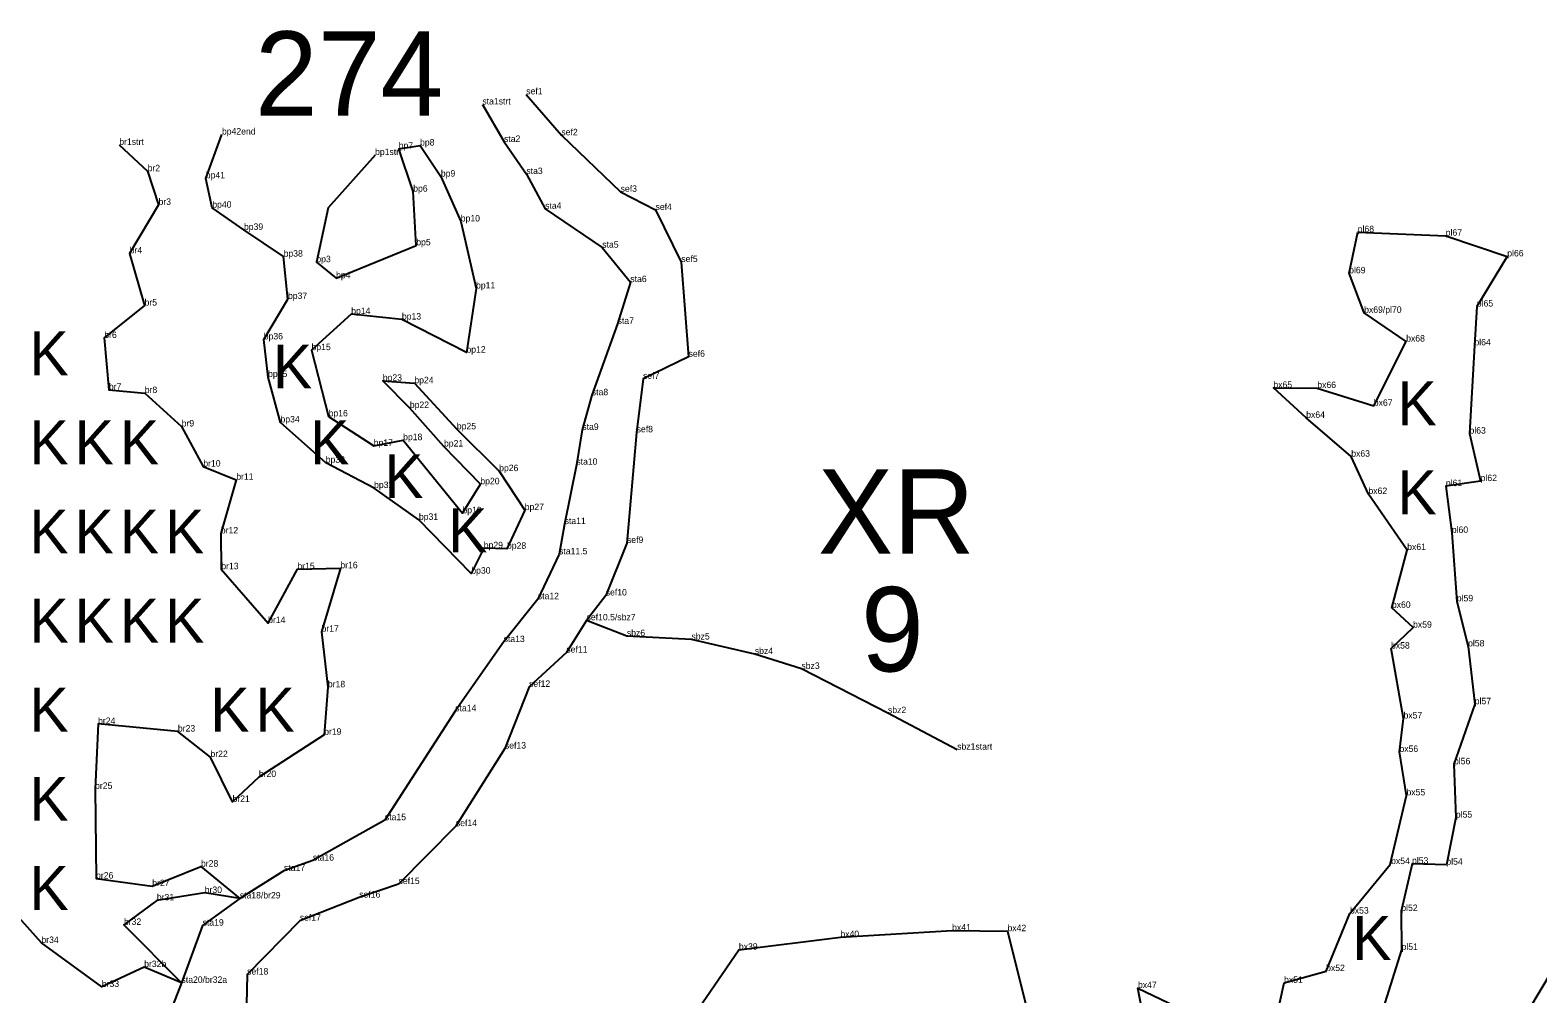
# Model space of a CAD drawing. Extents: x 2072529 to 2268812, y 436423 to 470008.
# Drawn here: x 2233102 to 2234269, y 438303 to 439049 of the extents above; entities that cross this region are included whole.
import ezdxf

# ---------------------------------------------------------------- set-up
doc = ezdxf.new("R2010")
doc.units = 0
for name, color, linetype in [('Old_Level_10', 7, 'Continuous'), ('Old_Level_20', 7, 'Continuous'), ('Old_Level_52', 7, 'Continuous'), ('Old_Level_55', 7, 'Continuous'), ('Old_Level_60', 7, 'Continuous'), ('Old_Level_62', 7, 'Continuous')]:
    doc.layers.add(name, color=color, linetype=linetype)

msp = doc.modelspace()

# ---------------------------------------------------------------- linework, layer by layer
at = {"layer": 'Old_Level_10'}
for points in [[(2233452.149, 438991.664), (2233468.903, 438962.649), (2233486.215, 438937.777), (2233500.705, 438910.853), (2233544.956, 438880.766), (2233566.694, 438854.085), (2233556.825, 438821.757), (2233536.872, 438766.484), (2233529.517, 438739.646), (2233524.919, 438712.662), (2233515.837, 438666.685), (2233511.521, 438643.301), (2233495.079, 438608.514), (2233468.612, 438575.331), (2233431.11, 438521.764), (2233376.668, 438437.394), (2233320.946, 438406.056), (2233298.574, 438398.116), (2233264.347, 438376.794), (2233235.564, 438355.78), (2233219.222, 438311.431), (2233210.7, 438289.635)], [(2233486.125, 438999.503), (2233513.334, 438967.786), (2233559.17, 438924.007), (2233586.216, 438909.965), (2233606.162, 438869.63), (2233611.796, 438796.228), (2233576.522, 438779.169), (2233571.575, 438737.748), (2233564.095, 438652.028), (2233547.637, 438611.403), (2233532.819, 438592.148), (2233517.163, 438567.199), (2233488.294, 438540.647), (2233469.596, 438492.881), (2233431.643, 438432.798), (2233387.241, 438387.931), (2233356.82, 438377.469), (2233310.807, 438359.523), (2233270.05, 438317.862), (2233268.69, 438260.03)], [(2233819.709, 438491.998), (2233766.143, 438520.289), (2233699.145, 438554.56), (2233663.079, 438566.07), (2233614.029, 438577.308), (2233564.004, 438579.97), (2233532.819, 438592.148)]]:
    msp.add_lwpolyline(points, dxfattribs=at)
at = {"layer": 'Old_Level_20'}
for p, q in [((2233452.149, 438991.664), (2233452.149, 438991.664)), ((2233486.125, 438999.503), (2233486.125, 438999.503)), ((2233250.54, 438968.368), (2233250.54, 438968.368)), ((2233513.334, 438967.786), (2233513.334, 438967.786)), ((2233171.058, 438960.351), (2233171.058, 438960.351)), ((2233387.354, 438957.417), (2233387.354, 438957.417)), ((2233403.912, 438959.866), (2233403.912, 438959.866)), ((2233468.903, 438962.649), (2233468.903, 438962.649)), ((2233193.012, 438939.927), (2233193.012, 438939.927)), ((2233238.028, 438934.445), (2233238.028, 438934.445)), ((2233420.007, 438935.811), (2233420.007, 438935.811)), ((2233486.215, 438937.777), (2233486.215, 438937.777)), ((2233398.611, 438924.169), (2233398.611, 438924.169)), ((2233559.17, 438924.007), (2233559.17, 438924.007)), ((2233201.424, 438913.897), (2233201.424, 438913.897)), ((2233243.053, 438911.718), (2233243.053, 438911.718)), ((2233500.705, 438910.853), (2233500.705, 438910.853)), ((2233586.216, 438909.965), (2233586.216, 438909.965)), ((2233435.402, 438901.032), (2233435.402, 438901.032)), ((2233267.568, 438894.505), (2233267.568, 438894.505)), ((2234129.797, 438892.773), (2234129.797, 438892.773)), ((2234197.922, 438889.97), (2234197.922, 438889.97)), ((2233179.099, 438876.325), (2233179.099, 438876.325)), ((2233298.26, 438873.801), (2233298.26, 438873.801)), ((2233400.966, 438882.567), (2233400.966, 438882.567)), ((2233544.956, 438880.766), (2233544.956, 438880.766)), ((2234245.56, 438873.979), (2234245.56, 438873.979)), ((2233323.625, 438869.522), (2233323.625, 438869.522)), ((2233606.162, 438869.63), (2233606.162, 438869.63)), ((2233338.88, 438857.064), (2233338.88, 438857.064)), ((2233566.694, 438854.085), (2233566.694, 438854.085)), ((2234123.163, 438860.908), (2234123.163, 438860.908)), ((2233301.659, 438841.001), (2233301.659, 438841.001)), ((2233447.245, 438849.142), (2233447.245, 438849.142)), ((2233190.601, 438835.952), (2233190.601, 438835.952)), ((2233350.609, 438829.324), (2233350.609, 438829.324)), ((2234134.774, 438830.293), (2234134.774, 438830.293)), ((2234221.981, 438835.186), (2234221.981, 438835.186)), ((2233389.864, 438825.117), (2233389.864, 438825.117)), ((2233556.825, 438821.757), (2233556.825, 438821.757)), ((2233159.429, 438810.809), (2233159.429, 438810.809)), ((2233282.914, 438809.689), (2233282.914, 438809.689)), ((2234167.302, 438808.062), (2234167.302, 438808.062)), ((2234220.158, 438805.076), (2234220.158, 438805.076)), ((2233319.872, 438801.388), (2233319.872, 438801.388)), ((2233439.817, 438799.483), (2233439.817, 438799.483)), ((2233611.796, 438796.228), (2233611.796, 438796.228)), ((2233286.242, 438780.557), (2233286.242, 438780.557)), ((2233163.015, 438770.697), (2233163.015, 438770.697)), ((2233190.8, 438768.172), (2233190.8, 438768.172)), ((2233375.063, 438777.665), (2233375.063, 438777.665)), ((2233399.495, 438775.737), (2233399.495, 438775.737)), ((2233576.522, 438779.169), (2233576.522, 438779.169)), ((2234064.502, 438772.209), (2234064.502, 438772.209)), ((2234098.507, 438772.049), (2234098.507, 438772.049)), ((2233395.99, 438756.593), (2233395.99, 438756.593)), ((2233536.872, 438766.484), (2233536.872, 438766.484)), ((2234142.245, 438758.284), (2234142.245, 438758.284)), ((2233295.86, 438745.435), (2233295.86, 438745.435)), ((2233333.112, 438750.109), (2233333.112, 438750.109)), ((2234089.931, 438748.963), (2234089.931, 438748.963)), ((2233219.337, 438742.292), (2233219.337, 438742.292)), ((2233432.367, 438740.095), (2233432.367, 438740.095)), ((2233529.517, 438739.646), (2233529.517, 438739.646)), ((2233571.575, 438737.748), (2233571.575, 438737.748)), ((2234216.328, 438736.768), (2234216.328, 438736.768)), ((2233368.001, 438727.299), (2233368.001, 438727.299)), ((2233390.805, 438731.689), (2233390.805, 438731.689)), ((2233422.421, 438726.764), (2233422.421, 438726.764)), ((2233236.091, 438711.257), (2233236.091, 438711.257)), ((2233330.864, 438714.212), (2233330.864, 438714.212)), ((2233524.919, 438712.662), (2233524.919, 438712.662)), ((2234124.787, 438718.917), (2234124.787, 438718.917)), ((2233261.633, 438701.078), (2233261.633, 438701.078)), ((2233465.139, 438707.705), (2233465.139, 438707.705)), ((2234224.963, 438699.989), (2234224.963, 438699.989)), ((2233368.313, 438694.596), (2233368.313, 438694.596)), ((2233450.581, 438697.522), (2233450.581, 438697.522)), ((2234138.111, 438689.97), (2234138.111, 438689.97)), ((2234198.007, 438696.097), (2234198.007, 438696.097)), ((2233436.707, 438675.091), (2233436.707, 438675.091)), ((2233484.94, 438677.54), (2233484.94, 438677.54)), ((2233403.011, 438669.957), (2233403.011, 438669.957)), ((2233515.837, 438666.685), (2233515.837, 438666.685)), ((2233249.693, 438659.447), (2233249.693, 438659.447)), ((2233564.095, 438652.028), (2233564.095, 438652.028)), ((2234202.646, 438659.862), (2234202.646, 438659.862)), ((2233453.224, 438647.979), (2233453.224, 438647.979)), ((2233471.201, 438647.572), (2233471.201, 438647.572)), ((2233511.521, 438643.301), (2233511.521, 438643.301)), ((2234168.109, 438646.6), (2234168.109, 438646.6)), ((2233250.028, 438631.711), (2233250.028, 438631.711)), ((2233308.925, 438631.758), (2233308.925, 438631.758)), ((2233342.212, 438632.512), (2233342.212, 438632.512)), ((2233443.579, 438628.34), (2233443.579, 438628.34)), ((2233495.079, 438608.514), (2233495.079, 438608.514)), ((2233547.637, 438611.403), (2233547.637, 438611.403)), ((2234206.503, 438606.874), (2234206.503, 438606.874)), ((2234156.263, 438601.829), (2234156.263, 438601.829)), ((2233286.303, 438590.049), (2233286.303, 438590.049)), ((2233327.623, 438583.344), (2233327.623, 438583.344)), ((2233532.819, 438592.148), (2233532.819, 438592.148)), ((2234172.653, 438586.501), (2234172.653, 438586.501)), ((2233468.612, 438575.331), (2233468.612, 438575.331)), ((2233564.004, 438579.97), (2233564.004, 438579.97)), ((2233614.029, 438577.308), (2233614.029, 438577.308)), ((2234155.584, 438570.281), (2234155.584, 438570.281)), ((2234215.251, 438571.962), (2234215.251, 438571.962)), ((2233517.163, 438567.199), (2233517.163, 438567.199)), ((2233663.079, 438566.07), (2233663.079, 438566.07)), ((2233699.145, 438554.56), (2233699.145, 438554.56)), ((2233332.548, 438540.298), (2233332.548, 438540.298)), ((2233488.294, 438540.647), (2233488.294, 438540.647)), ((2234220.377, 438527.179), (2234220.377, 438527.179)), ((2233154.634, 438511.906), (2233154.634, 438511.906)), ((2233431.11, 438521.764), (2233431.11, 438521.764)), ((2233766.143, 438520.289), (2233766.143, 438520.289)), ((2234165.255, 438516.151), (2234165.255, 438516.151)), ((2233216.434, 438506.06), (2233216.434, 438506.06)), ((2233329.678, 438503.54), (2233329.678, 438503.54)), ((2233469.596, 438492.881), (2233469.596, 438492.881)), ((2233819.709, 438491.998), (2233819.709, 438491.998)), ((2234162.115, 438490.258), (2234162.115, 438490.258)), ((2233241.656, 438486.323), (2233241.656, 438486.323)), ((2234204.321, 438480.7), (2234204.321, 438480.7)), ((2233279.123, 438470.844), (2233279.123, 438470.844)), ((2233152.309, 438461.639), (2233152.309, 438461.639)), ((2234167.55, 438456.6), (2234167.55, 438456.6)), ((2233258.712, 438451.546), (2233258.712, 438451.546)), ((2233376.668, 438437.394), (2233376.668, 438437.394)), ((2233431.643, 438432.798), (2233431.643, 438432.798)), ((2234205.768, 438439.368), (2234205.768, 438439.368)), ((2233320.946, 438406.056), (2233320.946, 438406.056)), ((2233234.306, 438401.459), (2233234.306, 438401.459)), ((2233298.574, 438398.116), (2233298.574, 438398.116)), ((2234154.999, 438403.07), (2234154.999, 438403.07)), ((2234171.844, 438403.686), (2234171.844, 438403.686)), ((2234198.431, 438402.887), (2234198.431, 438402.887)), ((2233153.079, 438392.206), (2233153.079, 438392.206)), ((2233196.547, 438386.332), (2233196.547, 438386.332)), ((2233387.241, 438387.931), (2233387.241, 438387.931)), ((2233200.165, 438375.307), (2233200.165, 438375.307)), ((2233237.196, 438381.029), (2233237.196, 438381.029)), ((2233264.347, 438376.794), (2233264.347, 438376.794)), ((2233264.347, 438376.794), (2233264.347, 438376.794)), ((2233356.82, 438377.469), (2233356.82, 438377.469)), ((2233310.807, 438359.523), (2233310.807, 438359.523)), ((2234123.796, 438365.08), (2234123.796, 438365.08)), ((2234163.55, 438367.073), (2234163.55, 438367.073)), ((2233174.653, 438356.346), (2233174.653, 438356.346)), ((2233235.564, 438355.78), (2233235.564, 438355.78)), ((2233815.783, 438351.891), (2233815.783, 438351.891)), ((2233858.656, 438351.453), (2233858.656, 438351.453)), ((2233110.769, 438342.307), (2233110.769, 438342.307)), ((2233650.735, 438337.127), (2233650.735, 438337.127)), ((2233729.33, 438346.824), (2233729.33, 438346.824)), ((2234163.752, 438336.952), (2234163.752, 438336.952)), ((2233190.348, 438323.661), (2233190.348, 438323.661)), ((2233270.05, 438317.862), (2233270.05, 438317.862)), ((2234105.343, 438320.55), (2234105.343, 438320.55)), ((2233157.542, 438308.254), (2233157.542, 438308.254)), ((2233219.222, 438311.431), (2233219.222, 438311.431)), ((2233219.222, 438311.431), (2233219.222, 438311.431)), ((2233959.691, 438307.398), (2233959.691, 438307.398)), ((2234072.757, 438311.451), (2234072.757, 438311.451))]:
    msp.add_line(p, q, dxfattribs=at)
at = {"layer": 'Old_Level_52'}
for points in [[(2233369.084, 438952.484), (2233332.653, 438911.674), (2233323.625, 438869.522), (2233338.88, 438857.064), (2233400.966, 438882.567), (2233398.611, 438924.169), (2233387.354, 438957.417), (2233403.912, 438959.866), (2233420.007, 438935.811), (2233435.402, 438901.032), (2233447.245, 438849.142), (2233439.817, 438799.483), (2233389.864, 438825.117), (2233350.609, 438829.324), (2233319.872, 438801.388), (2233333.112, 438750.109), (2233368.001, 438727.299), (2233390.805, 438731.689), (2233436.707, 438675.091), (2233450.581, 438697.522), (2233422.421, 438726.764), (2233395.99, 438756.593), (2233375.063, 438777.665), (2233399.495, 438775.737), (2233432.367, 438740.095), (2233465.139, 438707.705), (2233484.94, 438677.54), (2233471.201, 438647.572), (2233453.224, 438647.979), (2233443.579, 438628.34), (2233403.011, 438669.957), (2233368.313, 438694.596), (2233330.864, 438714.212), (2233295.86, 438745.435), (2233286.242, 438780.557), (2233282.914, 438809.689), (2233301.659, 438841.001), (2233298.26, 438873.801), (2233267.568, 438894.505), (2233243.053, 438911.718), (2233238.028, 438934.445), (2233250.54, 438968.368)], [(2233171.058, 438960.351), (2233193.012, 438939.927), (2233201.424, 438913.897), (2233179.099, 438876.325), (2233190.601, 438835.952), (2233159.429, 438810.809), (2233163.015, 438770.697), (2233190.8, 438768.172), (2233219.337, 438742.292), (2233236.091, 438711.257), (2233261.633, 438701.078), (2233249.693, 438659.447), (2233250.028, 438631.711), (2233286.303, 438590.049), (2233308.925, 438631.758), (2233342.212, 438632.512), (2233327.623, 438583.344), (2233332.548, 438540.298), (2233329.678, 438503.54), (2233279.123, 438470.844), (2233258.712, 438451.546), (2233241.656, 438486.323), (2233216.434, 438506.06), (2233154.634, 438511.906), (2233152.309, 438461.639), (2233153.079, 438392.206), (2233196.547, 438386.332), (2233234.306, 438401.459), (2233264.347, 438376.794), (2233237.196, 438381.029), (2233200.165, 438375.307), (2233174.653, 438356.346), (2233219.222, 438311.431), (2233190.348, 438323.661), (2233157.542, 438308.254), (2233110.769, 438342.307), (2233071.236, 438386.296)], [(2234059.944, 438252.781), (2234072.757, 438311.451), (2234105.343, 438320.55), (2234123.796, 438365.08), (2234154.999, 438403.07), (2234167.55, 438456.6), (2234162.115, 438490.258), (2234165.255, 438516.151), (2234155.584, 438570.281), (2234172.653, 438586.501), (2234156.263, 438601.829), (2234168.109, 438646.6), (2234138.111, 438689.97), (2234124.787, 438718.917), (2234089.931, 438748.963), (2234064.502, 438772.209), (2234098.507, 438772.049), (2234142.245, 438758.284), (2234167.302, 438808.062), (2234134.774, 438830.293), (2234123.163, 438860.908), (2234129.797, 438892.773), (2234197.922, 438889.97), (2234245.56, 438873.979), (2234221.981, 438835.186), (2234220.158, 438805.076), (2234216.328, 438736.768), (2234224.963, 438699.989), (2234198.007, 438696.097), (2234202.646, 438659.862), (2234206.503, 438606.874)], [(2234206.503, 438606.874), (2234215.251, 438571.962), (2234220.377, 438527.179), (2234204.321, 438480.7), (2234205.768, 438439.368), (2234198.431, 438402.887), (2234171.844, 438403.686), (2234163.55, 438367.073), (2234163.752, 438336.952), (2234149.394, 438291.748), (2234133.006, 438274.68), (2234116.863, 438241.327), (2234090.908, 438214.156), (2234094.319, 438184.72), (2234104.509, 438141.529), (2234133.818, 438128.749), (2234182.336, 438154.843), (2234195.999, 438171.358), (2234239.707, 438238.048), (2234253.57, 438275.929), (2234280.543, 438321.152)], [(2233613.074, 438282.026), (2233650.735, 438337.127), (2233729.33, 438346.824), (2233815.783, 438351.891), (2233858.656, 438351.453), (2233874.615, 438287.265)], [(2233965.718, 438275.421), (2233959.691, 438307.398), (2233989.311, 438293.233)]]:
    msp.add_lwpolyline(points, dxfattribs=at)

# ---------------------------------------------------------------- texts
at = {"layer": 'Old_Level_55'}
for p in [(2233101.528, 438781.933), (2233290.056, 438771.751), (2234160.577, 438743.244), (2233101.528, 438712.933), (2233136.528, 438712.933), (2233171.528, 438712.933), (2233318.795, 438713.022), (2233376.275, 438686.781), (2234160.577, 438674.244), (2233101.528, 438643.933), (2233136.528, 438643.933), (2233171.528, 438643.933), (2233206.528, 438643.933), (2233425.632, 438644.921), (2233101.528, 438574.933), (2233136.528, 438574.933), (2233171.528, 438574.933), (2233206.528, 438574.933), (2233101.528, 438505.933), (2233241.528, 438505.933), (2233276.528, 438505.933), (2233101.528, 438436.933), (2233101.528, 438367.933), (2234125.577, 438329.244)]:
    msp.add_text('K', height=34, dxfattribs=at).set_placement(p)
at = {"layer": 'Old_Level_60'}
for s, p in [('sef1', (2233486.125, 438999.503)), ('sta1strt', (2233452.149, 438991.664)), ('bp42end', (2233250.54, 438968.368)), ('sta2', (2233468.903, 438962.649)), ('sef2', (2233513.334, 438967.786)), ('br1strt', (2233171.058, 438960.351)), ('bp1strt', (2233369.084, 438952.484)), ('bp7', (2233387.354, 438957.417)), ('bp8', (2233403.912, 438959.866)), ('br2', (2233193.012, 438939.927)), ('sta3', (2233486.215, 438937.777)), ('bp41', (2233238.028, 438934.445)), ('bp9', (2233420.007, 438935.811)), ('bp6', (2233398.611, 438924.169)), ('sef3', (2233559.17, 438924.007)), ('br3', (2233201.424, 438913.897)), ('bp40', (2233243.053, 438911.718)), ('sta4', (2233500.705, 438910.853)), ('sef4', (2233586.216, 438909.965)), ('bp39', (2233267.568, 438894.505)), ('bp10', (2233435.402, 438901.032)), ('pl68', (2234129.797, 438892.773)), ('bp5', (2233400.966, 438882.567)), ('sta5', (2233544.956, 438880.766)), ('pl67', (2234197.922, 438889.97)), ('br4', (2233179.099, 438876.325)), ('bp38', (2233298.26, 438873.801)), ('bp3', (2233323.625, 438869.522)), ('sef5', (2233606.162, 438869.63)), ('pl66', (2234245.56, 438873.979)), ('bp4', (2233338.88, 438857.064)), ('pl69', (2234123.163, 438860.908)), ('bp11', (2233447.245, 438849.142)), ('sta6', (2233566.694, 438854.085)), ('br5', (2233190.601, 438835.952)), ('bp37', (2233301.659, 438841.001)), ('pl65', (2234221.981, 438835.186)), ('bp14', (2233350.609, 438829.324)), ('bp13', (2233389.864, 438825.117)), ('sta7', (2233556.825, 438821.757)), ('bx69/pl70', (2234134.774, 438830.293)), ('br6', (2233159.429, 438810.809)), ('bp36', (2233282.914, 438809.689)), ('bp15', (2233319.872, 438801.388)), ('bp12', (2233439.817, 438799.483)), ('bx68', (2234167.302, 438808.062)), ('pl64', (2234220.158, 438805.076)), ('sef6', (2233611.796, 438796.228)), ('bp35', (2233286.242, 438780.557)), ('bp23', (2233375.063, 438777.665)), ('bp24', (2233399.495, 438775.737)), ('sef7', (2233576.522, 438779.169)), ('br7', (2233163.015, 438770.697)), ('br8', (2233190.8, 438768.172)), ('sta8', (2233536.872, 438766.484)), ('bx65', (2234064.502, 438772.209)), ('bx66', (2234098.507, 438772.049)), ('bp22', (2233395.99, 438756.593)), ('bx67', (2234142.245, 438758.284)), ('br9', (2233219.337, 438742.292)), ('bp34', (2233295.86, 438745.435)), ('bp16', (2233333.112, 438750.109)), ('bp25', (2233432.367, 438740.095)), ('sta9', (2233529.517, 438739.646)), ('bx64', (2234089.931, 438748.963)), ('bp18', (2233390.805, 438731.689)), ('sef8', (2233571.575, 438737.748)), ('pl63', (2234216.328, 438736.768)), ('bp17', (2233368.001, 438727.299)), ('bp21', (2233422.421, 438726.764)), ('bx63', (2234124.787, 438718.917)), ('br10', (2233236.091, 438711.257)), ('bp33', (2233330.864, 438714.212)), ('bp26', (2233465.139, 438707.705)), ('sta10', (2233524.919, 438712.662)), ('br11', (2233261.633, 438701.078)), ('bp32', (2233368.313, 438694.596)), ('bp20', (2233450.581, 438697.522)), ('pl61', (2234198.007, 438696.097)), ('pl62', (2234224.963, 438699.989)), ('bx62', (2234138.111, 438689.97)), ('bp31', (2233403.011, 438669.957)), ('bp19', (2233436.707, 438675.091)), ('bp27', (2233484.94, 438677.54)), ('br12', (2233249.693, 438659.447)), ('sta11', (2233515.837, 438666.685)), ('pl60', (2234202.646, 438659.862)), ('bp29', (2233453.224, 438647.979)), ('bp28', (2233471.201, 438647.572)), ('sef9', (2233564.095, 438652.028)), ('bx61', (2234168.109, 438646.6)), ('sta11.5', (2233511.521, 438643.301)), ('br13', (2233250.028, 438631.711)), ('br15', (2233308.925, 438631.758)), ('br16', (2233342.212, 438632.512)), ('bp30', (2233443.579, 438628.34)), ('sef10', (2233547.637, 438611.403)), ('sta12', (2233495.079, 438608.514)), ('bx60', (2234156.263, 438601.829)), ('pl59', (2234206.503, 438606.874)), ('br14', (2233286.303, 438590.049)), ('sef10.5/sbz7', (2233532.819, 438592.148)), ('br17', (2233327.623, 438583.344)), ('sbz6', (2233564.004, 438579.97)), ('sbz5', (2233614.029, 438577.308)), ('bx59', (2234172.653, 438586.501)), ('sta13', (2233468.612, 438575.331)), ('sef11', (2233517.163, 438567.199)), ('sbz4', (2233663.079, 438566.07)), ('bx58', (2234155.584, 438570.281)), ('pl58', (2234215.251, 438571.962)), ('sbz3', (2233699.145, 438554.56)), ('br18', (2233332.548, 438540.298)), ('sef12', (2233488.294, 438540.647)), ('sta14', (2233431.11, 438521.764)), ('sbz2', (2233766.143, 438520.289)), ('pl57', (2234220.377, 438527.179)), ('br24', (2233154.634, 438511.906)), ('br23', (2233216.434, 438506.06)), ('bx57', (2234165.255, 438516.151)), ('br19', (2233329.678, 438503.54)), ('br22', (2233241.656, 438486.323)), ('sef13', (2233469.596, 438492.881)), ('sbz1start', (2233819.709, 438491.998)), ('bx56', (2234162.115, 438490.258)), ('br20', (2233279.123, 438470.844)), ('pl56', (2234204.321, 438480.7)), ('br25', (2233152.309, 438461.639)), ('br21', (2233258.712, 438451.546)), ('bx55', (2234167.55, 438456.6)), ('sta15', (2233376.668, 438437.394)), ('pl55', (2234205.768, 438439.368)), ('sef14', (2233431.643, 438432.798)), ('br28', (2233234.306, 438401.459)), ('sta16', (2233320.946, 438406.056)), ('bx54', (2234155.636, 438403.39)), ('pl53', (2234171.844, 438403.686)), ('pl54', (2234198.431, 438402.887)), ('br26', (2233153.079, 438392.206)), ('sta17', (2233298.574, 438398.116)), ('br27', (2233196.547, 438386.332)), ('br30', (2233237.196, 438381.029)), ('sef16', (2233356.82, 438377.469)), ('sef15', (2233387.241, 438387.931)), ('br31', (2233200.165, 438375.307)), ('sta18/br29', (2233264.347, 438376.794)), ('sta18/br29', (2233264.347, 438376.794)), ('pl52', (2234163.55, 438367.073)), ('br32', (2233174.653, 438356.346)), ('sta19', (2233235.564, 438355.78)), ('sef17', (2233310.807, 438359.523)), ('bx53', (2234123.796, 438365.08)), ('br34', (2233110.769, 438342.307)), ('bx40', (2233729.33, 438346.824)), ('bx41', (2233815.783, 438351.891)), ('bx42', (2233858.656, 438351.453)), ('bx39', (2233650.735, 438337.127)), ('pl51', (2234163.752, 438336.952)), ('br32b', (2233190.348, 438323.661)), ('bx52', (2234105.343, 438320.55)), ('br33', (2233157.542, 438308.254)), ('sta20/br32a', (2233219.222, 438311.431)), ('sta20/br32a', (2233219.222, 438311.431)), ('sef18', (2233270.05, 438317.862)), ('bx47', (2233959.691, 438307.398)), ('bx51', (2234072.757, 438311.451))]:
    msp.add_text(s, height=5, dxfattribs=at).set_placement(p)
at = {"layer": 'Old_Level_62'}
for s, p in [('274', (2233276.109, 438982.898)), ('XR', (2233711.881, 438643.773)), ('9', (2233745.302, 438552.625))]:
    msp.add_text(s, height=65.34, dxfattribs=at).set_placement(p)

doc.saveas('drawing.dxf')
